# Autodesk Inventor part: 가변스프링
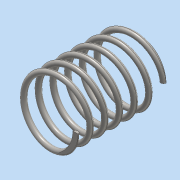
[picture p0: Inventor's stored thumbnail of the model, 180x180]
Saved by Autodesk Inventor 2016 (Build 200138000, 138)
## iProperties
Created: 2018-11
Part Number: 가변스프링
Material: 스테인레스 스틸
Document SubType Name: Modeling
Designer: user
Density: 8 g/cm^3
Appearance: 반연마
Mass: 84.2201 g
Surface Area: 106.447 cm^2
Volume: 10.5275 cm^3
Author: user
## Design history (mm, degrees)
sketch "스케치2"
  geometry: L1 (0, 0)-(22.5, 0); L2 (22.5, 0)-(22.5, 67.25); L3 (22.5, 67.25)-(0, 67.25); L4 (0, 67.25)-(0, 0); C1 r 2 at (22.5, 0)
  constraints: 8 end point, 2 parallel, 1 centre point, 1 coincident, 1 horizontal, 1 perpendicular
  dimensions: "d3" = 22.5 distance of L3.end L2.end; "d4" = 67.25 distance of L2.end L1.end (derived); "d5" = 4 diameter of C1
feature "코일1" sketch "스케치2" pitch "d6" = 10; turns "d8" = 6; dims "d7" = 67.25 (= d4), "d9" = 0, angle "d10" = 90 deg, angle "d11" = 90 deg, "d12" = 0, "d13" = 0
sketch "스케치3"
  geometry: L1 (67.25, 34.625)-(0, 34.625); L2 (0, 34.625)-(0, -34.625); L3 (0, -34.625)-(67.25, -34.625); L4 (67.25, -34.625)-(67.25, 34.625); 2 further points
  constraints: 8 end point, 2 parallel, 1 coincident, 1 horizontal, 1 midpoint, 1 perpendicular
  dimensions: "d14" = 67.25 distance of L2.end L3.end (= d4); "d15" = 69.24925 distance of L3.end L1.start
extrude "돌출1" sketch "스케치3" stored distance "d16" = 100; taper "d17" = 0 deg
node "솔리드1"
